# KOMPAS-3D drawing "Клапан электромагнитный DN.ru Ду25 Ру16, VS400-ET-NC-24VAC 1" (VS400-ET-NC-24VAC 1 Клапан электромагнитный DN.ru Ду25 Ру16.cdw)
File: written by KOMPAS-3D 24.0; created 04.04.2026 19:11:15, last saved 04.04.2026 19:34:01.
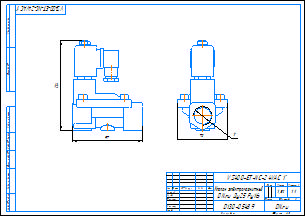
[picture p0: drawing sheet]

Document properties: c3d_UniqueCompID: ef56311e-7521-43dc-8291-0e6108b3d81d; Обозначение: VS400-ET-NC-220VAC 1; Наименование: Клапан электромагнитный DN.ru Ду25 Ру16; Автор: artio; Класс точности: c; Знак неуказанной шероховатости: Шероховатость не задана; Рассекать на разрезах: Да; c3d_UniqueCompID: ef56311e-7521-43dc-8291-0e6108b3d81d; Обозначение: VS400-ET-NC-220VAC 1-2; Наименование: Клапан электромагнитный DN.ru Ду15 Ру16; Автор: artio; Класс точности: c; Знак неуказанной шероховатости: Шероховатость не задана; Рассекать на разрезах: Да; c3d_UniqueCompID: ef56311e-7521-43dc-8291-0e6108b3d81d; Обозначение: VS400-ET-NC-220VAC 3-4; Наименование: Клапан электромагнитный DN.ru Ду20 Ру16; Автор: artio; Класс точности: c; Знак неуказанной шероховатости: Шероховатость не задана; Рассекать на разрезах: Да; c3d_UniqueCompID: ef56311e-7521-43dc-8291-0e6108b3d81d; Обозначение: VS400-ET-NC-220VAC 3-8; Наименование: Клапан электромагнитный DN.ru Ду10 Ру16; Автор: artio; Класс точности: c; Знак неуказанной шероховатости: Шероховатость не задана; Рассекать на разрезах: Да; Автор: artio; Форматы листов документа: A3; Полное имя файла: VS400-ET-NC-24VAC 1 Клапан электромагнитный DN.ru Ду25 Ру16.m3d; Масса: 1.524; Наименование: Клапан электромагнитный DN.ru Ду25 Ру16; Количество листов документа: 1; Примечание: D130-05489

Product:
- Body: Тело 1  | qty 1
    Масса: 1.76797
- Part/product: Клапан электромагнитный DN.ru Ду25 Ру16  | designation VS400-ET-NC-24VAC 1
    Масса: 1.524
    Раздел спецификации: Прочие изделия
    Примечание: D130-05489
    additional columns: ef56311e-7521-43dc-8291-0e6108b3d81d; VS400-ET-NC-220VAC 1; artio; c; Шероховатость не задана; Да

Views: Вид 1, Спереди
Referenced files in C:\Users\artio\OneDrive\Рабочий стол\Клапан электромагнитный DN.ru\VS400-ET-NC\VS400-ET-NC-24VDC\: VS400-ET-NC-24VDC 3-8 Клапан электромагнитный DN.ru Ду10 Ру16.m3d
Referenced files in C:\Users\artio\OneDrive\Рабочий стол\Клапан электромагнитный DN.ru\VS400\VS400-ET-NC\VS400-ET-NC-24VAC\Ду25\: VS400-ET-NC-24VAC 1 Клапан электромагнитный DN.ru Ду25 Ру16.m3d
Referenced files in C:\Users\artio\OneDrive\Рабочий стол\Клапан электромагнитный DN.ru\VS400-ET-NC\: VS400-ET-NC-24VDC 3-8 Клапан электромагнитный DN.ru Ду10 Ру16.cdw
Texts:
  VS400-ET-NC-24VAC 1
  Клапан электромагнитный
  DN.ru Ду25 Ру16
  VS400-ET-NC-24VAC 1"
  VS400-ET-NC-24VAC 1"-
  Клапан электромагнитный DN.ru Ду25 Ру16
  VS400-ET-NC-24VAC 1 Клапан электромагнитный DN.ru Ду25 Ру16
Dimensions and other numbers on the sheet: 0; 3; 2; 4; 70; 1:1; 1; 1,52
